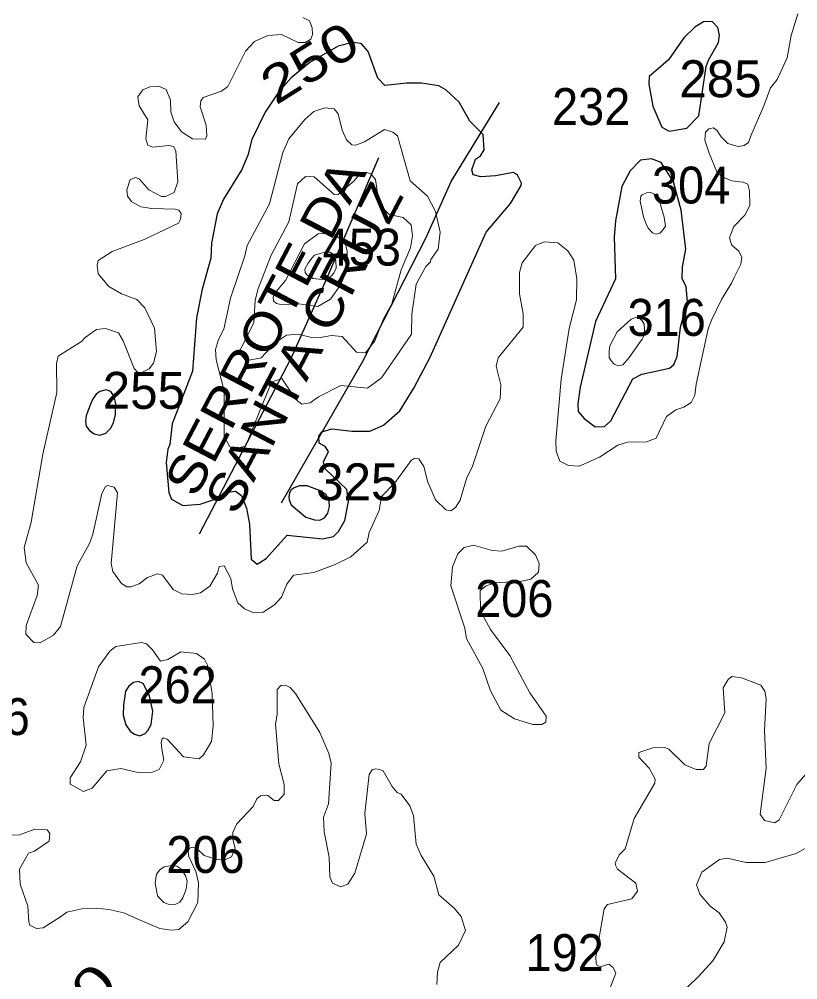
# Model space of a CAD drawing. Extents: x 499.9 to 555.3, y 9281.5 to 9336.8.
# Drawn here: x 532.96 to 536.335, y 9313.886 to 9318.048 of the extents above; entities that cross this region are included whole.
import ezdxf
from ezdxf.enums import TextEntityAlignment as Align

# ---------------------------------------------------------------- set-up
doc = ezdxf.new("R2010")
doc.units = 0
doc.header["$LTSCALE"] = 0.064
for name, color, linetype, lineweight in [('1', 7, 'Continuous', 25), ('2', 7, 'Continuous', 13), ('26', 7, 'Continuous', 25)]:
    doc.layers.add(name, color=color, linetype=linetype, lineweight=lineweight)
doc.layers.add('21', color=7, linetype='Continuous')
doc.layers.add('61', color=7, linetype='Continuous')

msp = doc.modelspace()

# ---------------------------------------------------------------- linework, layer by layer
at = {"layer": '1'}
for points in [[(535.8544, 9317.5765), (535.9065, 9317.6293), (535.9382, 9317.8433), (535.9476, 9317.8711), (535.9909, 9317.9476), (535.9952, 9317.9793), (535.9889, 9318.0125), (535.9645, 9318.0388), (535.9266, 9318.037), (535.889, 9318.0138), (535.8404, 9317.9681), (535.7749, 9317.872), (535.7521, 9317.8519), (535.6906, 9317.8007), (535.6888, 9317.7675), (535.706, 9317.6708), (535.7456, 9317.58), (535.7777, 9317.5636)], [(534.4723, 9317.9086), (534.4426, 9317.9428), (534.4053, 9317.9469), (534.3422, 9317.9319), (534.2194, 9317.8603), (534.1392, 9317.7937), (534.0832, 9317.7318), (534.0264, 9317.6453), (533.9684, 9317.5274), (533.9505, 9317.4598), (533.9253, 9317.3969), (533.8455, 9317.2688), (533.8185, 9317.2051), (533.793, 9317.0778), (533.7911, 9317.0134), (533.7527, 9316.8785), (533.7279, 9316.7539), (533.7117, 9316.5231), (533.6235, 9316.2949), (533.6123, 9316.2054), (533.6035, 9316.1857), (533.5972, 9316.1271), (533.6078, 9315.9968), (533.6198, 9315.9688), (533.6684, 9315.9416), (533.7444, 9315.9466), (533.8136, 9315.9702), (533.8741, 9316.0005), (533.897, 9316.0029), (533.9236, 9315.9838), (533.9454, 9315.9295), (533.9583, 9315.8596), (533.9658, 9315.7079), (533.9913, 9315.6875), (534.03, 9315.7108), (534.122, 9315.8118), (534.2743, 9315.7962), (534.3222, 9315.8068), (534.3435, 9315.8277), (534.371, 9315.8766), (534.3868, 9315.9584), (534.3795, 9316.0102), (534.2863, 9316.1005), (534.2793, 9316.1304), (534.3008, 9316.1748), (534.2861, 9316.1972), (534.2597, 9316.2113), (534.2586, 9316.2408), (534.2721, 9316.2606), (534.3149, 9316.2738), (534.4022, 9316.2636), (534.4797, 9316.2634), (534.5392, 9316.2886), (534.6098, 9316.3511), (534.671, 9316.45), (534.7412, 9316.5837), (534.9847, 9317.1249), (535.0901, 9317.2498), (535.1364, 9317.3273), (535.1373, 9317.3379), (535.1195, 9317.3722), (535.1026, 9317.3845), (535.0241, 9317.3692), (534.9607, 9317.3646), (534.9281, 9317.3742), (534.9216, 9317.3952), (534.9379, 9317.4411), (534.9594, 9317.4568), (534.9751, 9317.4823), (534.9706, 9317.548), (534.9136, 9317.6063), (534.8671, 9317.6889), (534.8093, 9317.7419), (534.7791, 9317.7594), (534.7041, 9317.7717), (534.639, 9317.7717), (534.5452, 9317.7614), (534.514, 9317.7925)], [(535.6206, 9316.4906), (535.659, 9316.5098), (535.7787, 9316.5366), (535.7971, 9316.5522), (535.8124, 9316.586), (535.8261, 9316.7136), (535.8572, 9316.8242), (535.8514, 9316.8879), (535.8335, 9316.9242), (535.835, 9316.9753), (535.8497, 9317.0521), (535.8302, 9317.2209), (535.7969, 9317.344), (535.7428, 9317.4279), (535.701, 9317.4431), (535.6529, 9317.4372), (535.6089, 9317.3914), (535.5718, 9317.3231), (535.5454, 9317.1743), (535.539, 9317.1042), (535.5452, 9316.9226), (535.4587, 9316.7383), (535.3923, 9316.4531), (535.3815, 9316.3816), (535.3833, 9316.349), (535.4085, 9316.3174), (535.4562, 9316.2824), (535.4974, 9316.284), (535.5241, 9316.3079)], [(533.2701, 9316.3833), (533.2569, 9316.3505), (533.2506, 9316.3302), (533.2475, 9316.3068), (533.2506, 9316.2842), (533.2647, 9316.2655), (533.2849, 9316.2515), (533.3091, 9316.246), (533.3348, 9316.2546), (533.3551, 9316.2741), (533.3691, 9316.299), (533.3769, 9316.3357), (533.3785, 9316.3817), (533.3715, 9316.4129), (533.3567, 9316.4347), (533.3372, 9316.4417), (533.3091, 9316.4355), (533.2927, 9316.4238), (533.2771, 9316.4004)], [(534.1381, 9315.9435), (534.2022, 9315.8912), (534.2406, 9315.8784), (534.263, 9315.8773), (534.2833, 9315.888), (534.2983, 9315.9083), (534.3047, 9315.936), (534.3036, 9315.9617), (534.2887, 9315.9884), (534.2609, 9316.0065), (534.2075, 9316.0257), (534.1744, 9316.0257), (534.152, 9316.0182), (534.1381, 9316.0086), (534.1317, 9315.9958), (534.1285, 9315.9798), (534.1307, 9315.9649)], [(533.4178, 9315.1168), (533.4114, 9315.0774), (533.4101, 9315.0329), (533.4216, 9314.9909), (533.4407, 9314.9629), (533.4597, 9314.9502), (533.4826, 9314.9426), (533.5055, 9314.9527), (533.517, 9314.9655), (533.5322, 9314.9922), (533.5386, 9315.0494), (533.5246, 9315.1155), (533.4992, 9315.1677), (533.4775, 9315.1779), (533.4559, 9315.174), (533.4343, 9315.1575), (533.4203, 9315.1372)]]:
    msp.add_lwpolyline(points, close=True, dxfattribs=at)
at = {"layer": '2'}
for points in [[(536.3346, 9318.0718), (536.3065, 9317.9773), (536.2887, 9317.8808), (536.245, 9317.7871), (536.2174, 9317.7502), (536.188, 9317.6723), (536.1319, 9317.5431), (536.1209, 9317.5135), (536.103, 9317.5013), (536.0762, 9317.4967), (536.0319, 9317.5104), (536.0023, 9317.5386), (535.9845, 9317.5677), (535.9677, 9317.5769), (535.9491, 9317.5739), (535.9357, 9317.5588), (535.9317, 9317.5242), (535.9512, 9317.4673), (535.9838, 9317.3864), (536.006, 9317.3672), (536.0481, 9317.3483), (536.099, 9317.3419), (536.1179, 9317.3337), (536.126, 9317.3048), (536.1274, 9317.2403), (536.1053, 9317.1989), (536.0584, 9317.15), (536.0386, 9317.102), (536.0476, 9317.0707), (536.0792, 9317.0437), (536.0927, 9317.0151), (536.0882, 9316.9866), (536.0597, 9316.9295), (536.0477, 9316.9038), (536.004, 9316.8334), (535.961, 9316.7443), (535.9469, 9316.707), (535.8945, 9316.4673), (535.8888, 9316.419)], [(533.2303, 9316.651), (533.2451, 9316.6696), (533.2942, 9316.7033), (533.3344, 9316.7084), (533.3906, 9316.6886), (533.4105, 9316.6551), (533.4582, 9316.5351), (533.4738, 9316.5167), (533.4908, 9316.5167), (533.5236, 9316.5334), (533.5414, 9316.5577), (533.5543, 9316.609), (533.5459, 9316.7094), (533.5047, 9316.7976), (533.4697, 9316.8341), (533.4031, 9316.8583), (533.3476, 9316.8898), (533.3025, 9316.945), (533.2981, 9316.9806), (533.3024, 9317.0023), (533.3632, 9317.0419), (533.5016, 9317.093), (533.6498, 9317.1646), (533.6584, 9317.1813), (533.6615, 9317.2061), (533.6516, 9317.2212), (533.6352, 9317.2257), (533.5343, 9317.2275), (533.4877, 9317.2351), (533.4477, 9317.2562), (533.4287, 9317.2816), (533.4259, 9317.3087), (533.4404, 9317.354), (533.465, 9317.3624), (533.4812, 9317.3553), (533.5215, 9317.3083), (533.5764, 9317.28), (533.594, 9317.2802), (533.6314, 9317.2975), (533.6467, 9317.3442), (533.6385, 9317.4781), (533.6292, 9317.4971), (533.609, 9317.5013), (533.5386, 9317.4933), (533.5171, 9317.5027), (533.5084, 9317.5306), (533.5174, 9317.6124), (533.48, 9317.6725), (533.4742, 9317.7114), (533.4956, 9317.7421), (533.5262, 9317.7555), (533.5653, 9317.7587), (533.5966, 9317.7433), (533.6156, 9317.6978), (533.6164, 9317.6476), (533.6311, 9317.6033), (533.6633, 9317.5599), (533.7112, 9317.5302), (533.7671, 9317.5287), (533.7736, 9317.5426), (533.7706, 9317.5895), (533.7442, 9317.6683), (533.747, 9317.6945), (533.7579, 9317.7089), (533.8368, 9317.7364), (533.8649, 9317.7565), (533.9401, 9317.9101), (533.9802, 9317.951), (534.0372, 9317.977), (534.0965, 9317.9816), (534.1696, 9317.9467), (534.1994, 9317.9467), (534.2233, 9317.9616), (534.231, 9317.9818), (534.2297, 9318.0109), (534.2188, 9318.0409), (534.1897, 9318.0562)], [(535.721, 9316.2323), (535.6789, 9316.217), (535.597, 9316.2151), (535.5556, 9316.2027), (535.4759, 9316.1503), (535.3869, 9316.1121), (535.3416, 9316.1151), (535.3032, 9316.1333), (535.2876, 9316.1771), (535.2859, 9316.2209), (535.3097, 9316.4882), (535.3437, 9316.7087), (535.3763, 9316.832), (535.3765, 9316.9226), (535.3638, 9317.0045), (535.3378, 9317.0447), (535.2951, 9317.0792), (535.2349, 9317.0841), (535.1979, 9317.0677), (535.1405, 9316.9933), (535.1285, 9316.9513), (535.1287, 9316.858), (535.1441, 9316.7722), (535.1444, 9316.7131), (535.0361, 9316.5811), (535.0268, 9316.5455), (535.0484, 9316.4643), (535.0455, 9316.4037), (534.9832, 9316.2845), (534.9232, 9316.1078), (534.9004, 9316.0617), (534.8716, 9315.9648), (534.8512, 9315.9321), (534.8306, 9315.918), (534.8094, 9315.9229), (534.7641, 9315.9651), (534.7308, 9316.0426), (534.7146, 9316.1094), (534.6921, 9316.143), (534.6717, 9316.1449), (534.6584, 9316.1355), (534.5882, 9316.0394), (534.5307, 9315.9805), (534.5207, 9315.9192), (534.4774, 9315.8238), (534.4676, 9315.7825), (534.3978, 9315.7184), (534.3296, 9315.6847), (534.237, 9315.6503), (534.1482, 9315.6386), (534.1194, 9315.6008), (534.0967, 9315.5436), (534.0666, 9315.5102), (534.0173, 9315.4786), (533.9768, 9315.4753), (533.9363, 9315.4928), (533.9073, 9315.5187), (533.8842, 9315.5799), (533.8775, 9315.6244), (533.8479, 9315.6802), (533.8267, 9315.6768), (533.8195, 9315.648), (533.7859, 9315.591), (533.7452, 9315.5629), (533.7103, 9315.5551), (533.6648, 9315.558), (533.6266, 9315.5768), (533.5814, 9315.6398), (533.5589, 9315.6451), (533.5153, 9315.6297), (533.4794, 9315.6009), (533.4445, 9315.5883), (533.4263, 9315.5887), (533.4037, 9315.6037), (533.3656, 9315.6555), (533.3585, 9315.69), (533.3852, 9315.9962), (533.3715, 9316.0206), (533.3425, 9316.0281), (533.3338, 9316.0227), (533.3185, 9315.9931), (533.2788, 9315.8173), (533.2641, 9315.776), (533.2109, 9315.6803), (533.139, 9315.417), (533.1079, 9315.3793), (533.0512, 9315.3465), (533.0234, 9315.3469), (532.9878, 9315.3838), (532.9894, 9315.4209), (533.0375, 9315.5508), (533.0431, 9315.5952), (532.9896, 9315.6925), (532.9814, 9315.7584), (533.0114, 9315.8682)], [(533.0114, 9315.8682), (533.0623, 9316.1636), (533.1227, 9316.4309), (533.1211, 9316.5566), (533.1292, 9316.5884), (533.2303, 9316.651)], [(535.8888, 9316.419), (535.8733, 9316.3877), (535.8412, 9316.3665), (535.8064, 9316.3551), (535.7657, 9316.327), (535.721, 9316.2323)], [(535.5179, 9313.8389), (535.547, 9313.9139), (535.5347, 9313.9396), (535.5156, 9313.9542), (535.4821, 9313.943), (535.4675, 9313.9463), (535.4608, 9313.9564), (535.4597, 9313.9853), (535.4961, 9314.1935), (535.5099, 9314.2123), (535.6159, 9314.2368), (535.6403, 9314.2704), (535.6337, 9314.3041), (535.554, 9314.3657), (535.5459, 9314.3796), (535.5438, 9314.3907), (535.5604, 9314.4266), (535.5871, 9314.4535), (535.6262, 9314.5847), (535.7154, 9314.7382), (535.7166, 9314.7548), (535.6903, 9314.8027), (535.6461, 9314.8508), (535.6464, 9314.8705), (535.7069, 9314.8908), (535.7591, 9314.8923), (535.7765, 9314.8855), (535.8453, 9314.8176), (535.895, 9314.7975), (535.9269, 9314.7977), (535.9373, 9314.8133), (535.9512, 9314.9092), (536.0195, 9315.043), (536.012, 9315.1512), (536.0336, 9315.1873), (536.0491, 9315.1995), (536.0911, 9315.1949), (536.1747, 9315.1632), (536.1916, 9315.1368), (536.1978, 9315.1036), (536.1914, 9314.9662), (536.1977, 9314.8019), (536.1724, 9314.603), (536.1901, 9314.5762), (536.236, 9314.5667), (536.2544, 9314.5787), (536.3316, 9314.7318), (536.3805, 9314.7891)], [(532.9161, 9314.5124), (532.9606, 9314.514), (533.0268, 9314.5389), (533.0806, 9314.536), (533.0924, 9314.5193), (533.0903, 9314.4865), (533.0255, 9314.4431), (532.9993, 9314.434), (532.9607, 9314.3651), (532.9637, 9314.2997), (532.9978, 9314.2055), (533.0014, 9314.1372), (533.0062, 9314.1222), (533.0354, 9314.108), (533.064, 9314.1111), (533.1393, 9314.159), (533.166, 9314.1782), (533.231, 9314.1931), (533.2928, 9314.1961), (533.3479, 9314.1908), (533.4127, 9314.1759), (533.4739, 9314.148), (533.5693, 9314.1078), (533.618, 9314.1002), (533.6519, 9314.1038), (533.691, 9314.1368), (533.7335, 9314.2208), (533.7373, 9314.3063), (533.7249, 9314.3558), (533.6944, 9314.4207), (533.692, 9314.4421), (533.6986, 9314.4569), (533.7114, 9314.4604), (533.7316, 9314.4533), (533.7618, 9314.4245), (533.8161, 9314.4075), (533.8486, 9314.4043), (533.8796, 9314.4181), (533.8962, 9314.4565), (533.8838, 9314.5011), (533.886, 9314.5241), (533.9029, 9314.5614), (533.9743, 9314.6365), (533.9894, 9314.6702), (534.0057, 9314.6836), (534.038, 9314.6839), (534.0646, 9314.6625), (534.0842, 9314.6634), (534.1077, 9314.6907), (534.1079, 9314.7319), (534.0858, 9314.8218), (534.0715, 9314.9929), (534.0778, 9315.035), (534.078, 9315.1234), (534.0786, 9315.1439), (534.0936, 9315.1608), (534.1137, 9315.163), (534.1348, 9315.1524), (534.1578, 9315.1259), (534.2627, 9314.9572), (534.3026, 9314.8669), (534.3117, 9314.8242), (534.301, 9314.6485), (534.2787, 9314.5901), (534.2818, 9314.5274), (534.2832, 9314.5196), (534.3038, 9314.4167), (534.307, 9314.3317), (534.3177, 9314.3049), (534.3535, 9314.288), (534.3851, 9314.3009)], [(534.3851, 9314.3009), (534.4141, 9314.3485), (534.466, 9314.5179), (534.4584, 9314.6063), (534.4774, 9314.7755), (534.49, 9314.7961)], [(534.49, 9314.7961), (534.5063, 9314.8003), (534.5222, 9314.7971), (534.5378, 9314.7915), (534.5763, 9314.723), (534.5979, 9314.6975), (534.6161, 9314.6899), (534.6538, 9314.6395), (534.6684, 9314.5974), (534.6812, 9314.4741), (534.7021, 9314.4249), (534.757, 9314.3347), (534.7786, 9314.254), (534.8448, 9314.1955), (534.8762, 9314.1595), (534.894, 9314.1), (534.8643, 9314.0355), (534.7847, 9313.9614), (534.7733, 9313.9194), (534.7701, 9313.8653)], [(536.3665, 9314.455), (536.3275, 9314.4325), (536.1939, 9314.3945), (536.1118, 9314.3945), (536.0291, 9314.4133), (535.9964, 9314.4073), (535.9184, 9314.3519), (535.8955, 9314.298), (535.91, 9314.2575), (535.9559, 9314.2051), (535.9936, 9314.1764), (536.0216, 9314.1352), (536.029, 9314.1137), (536.0164, 9314.0507), (535.9666, 9313.9679), (535.9049, 9313.8995), (535.8177, 9313.8166)]]:
    msp.add_lwpolyline(points, dxfattribs=at)
for points in [[(534.6624, 9316.7701), (534.6809, 9316.9008), (534.7221, 9316.9772), (534.7425, 9316.9962), (534.7438, 9317.0067), (534.7759, 9317.052), (534.7843, 9317.1256), (534.7649, 9317.2154), (534.7296, 9317.2819), (534.6541, 9317.3486), (534.5995, 9317.5422), (534.579, 9317.5584), (534.5427, 9317.5708), (534.4565, 9317.5165), (534.4192, 9317.5031), (534.4016, 9317.5045), (534.3787, 9317.5251), (534.3599, 9317.5673), (534.3425, 9317.6381), (534.325, 9317.6603), (534.2848, 9317.6649), (534.2365, 9317.6486), (534.1973, 9317.6141), (534.1285, 9317.5298), (534.1021, 9317.4701), (534.045, 9317.2483), (533.9473, 9317.0675), (533.9376, 9317.023), (533.876, 9316.8399), (533.8469, 9316.7055), (533.8231, 9316.6601), (533.8107, 9316.6171), (533.8135, 9316.5724), (533.8487, 9316.4373), (533.8487, 9316.2398), (533.8724, 9316.1954), (533.8996, 9316.1884), (533.9412, 9316.1986), (534.0542, 9316.476), (534.0987, 9316.4914), (534.1586, 9316.4006), (534.1852, 9316.3795), (534.2217, 9316.386), (534.2573, 9316.4125), (534.3541, 9316.4615), (534.4693, 9316.4494), (534.5303, 9316.4944), (534.6602, 9316.6841)], [(534.5753, 9316.8153), (534.6158, 9316.9616), (534.6564, 9317.0571), (534.665, 9317.1096), (534.6596, 9317.1578), (534.6236, 9317.189), (534.5643, 9317.2027), (534.5203, 9317.2474), (534.5047, 9317.3532), (534.4841, 9317.3785), (534.4629, 9317.3853), (534.4403, 9317.3827), (534.4121, 9317.3485), (534.3414, 9317.2866), (534.3245, 9317.2894), (534.2391, 9317.3652), (534.2015, 9317.367), (534.1669, 9317.3349), (534.1289, 9317.1709), (534.052, 9317.0262), (533.9936, 9316.8773), (533.9823, 9316.8288), (533.9771, 9316.7334), (533.9128, 9316.6052), (533.9428, 9316.5675), (534.0081, 9316.5809), (534.071, 9316.6474), (534.119, 9316.6793), (534.1701, 9316.683), (534.2214, 9316.6703), (534.2649, 9316.6689), (534.3134, 9316.6782), (534.3603, 9316.6734), (534.4224, 9316.6062), (534.4612, 9316.6024), (534.5015, 9316.6553), (534.5392, 9316.7493)], [(535.6522, 9317.26), (535.6659, 9317.1926), (535.6762, 9317.1641), (535.6865, 9317.1435), (535.7059, 9317.1229), (535.7207, 9317.1161), (535.7367, 9317.1218), (535.7481, 9317.1332), (535.7618, 9317.1515), (535.7561, 9317.1903), (535.7356, 9317.2588), (535.7264, 9317.2782), (535.7127, 9317.2908), (535.6956, 9317.2988), (535.6796, 9317.2965), (535.6602, 9317.2874), (535.6545, 9317.2811)], [(534.3093, 9316.8346), (534.3535, 9316.8993), (534.375, 9316.9481), (534.3825, 9316.9954), (534.3809, 9317.045), (534.3718, 9317.083), (534.3158, 9317.1207), (534.2552, 9317.1176), (534.1964, 9317.0752), (534.1148, 9316.9163), (534.0658, 9316.8601), (534.061, 9316.8433), (534.0623, 9316.8273), (534.0753, 9316.8167), (534.0945, 9316.8123), (534.1715, 9316.8153), (534.2543, 9316.8027)], [(534.293, 9316.9241), (534.3122, 9316.935), (534.3239, 9316.9475), (534.3339, 9316.9701), (534.3323, 9317.0018), (534.3247, 9317.0277), (534.308, 9317.0386), (534.2846, 9317.0386), (534.2638, 9317.0336), (534.2395, 9317.0261), (534.2287, 9317.0127), (534.2128, 9316.9918), (534.1978, 9316.9651), (534.1994, 9316.95), (534.2061, 9316.94), (534.2337, 9316.9241), (534.2729, 9316.9208)], [(535.5393, 9316.5541), (535.5496, 9316.5489), (535.563, 9316.5479), (535.5764, 9316.551), (535.6042, 9316.5829), (535.6486, 9316.6458), (535.6599, 9316.6623), (535.6692, 9316.6798), (535.6712, 9316.7045), (535.6692, 9316.7261), (535.6609, 9316.7406), (535.6506, 9316.7519), (535.6321, 9316.755), (535.6125, 9316.7488), (535.5517, 9316.6942), (535.5198, 9316.6334), (535.5167, 9316.6107), (535.5167, 9316.5819), (535.5259, 9316.5675)], [(534.8995, 9315.3646), (534.891, 9315.4099), (534.8312, 9315.5926), (534.8386, 9315.6749), (534.8611, 9315.7313), (534.8881, 9315.7597), (534.9292, 9315.7691), (535.0105, 9315.7458), (535.0524, 9315.7425), (535.1251, 9315.7647), (535.1588, 9315.7644), (535.1985, 9315.7275), (535.2142, 9315.6892), (535.2116, 9315.6528), (535.1774, 9315.6224), (535.1371, 9315.6137), (535.024, 9315.6057), (534.9845, 9315.5924), (534.9581, 9315.5726), (534.9595, 9315.4837), (535.0031, 9315.4033), (535.0865, 9315.2912), (535.1733, 9315.1291), (535.2438, 9315.0286), (535.2432, 9315.0021), (535.2258, 9314.9925), (535.1864, 9314.992), (535.1068, 9315.0165), (535.0483, 9315.054), (535.0035, 9315.1376), (534.9691, 9315.2348)], [(533.8007, 9314.9846), (533.7961, 9315.1244), (533.7767, 9315.2486), (533.7625, 9315.2759), (533.7283, 9315.2996), (533.6608, 9315.3064), (533.6035, 9315.2733), (533.5726, 9315.2671), (533.5383, 9315.3159), (533.5119, 9315.3421), (533.4899, 9315.3477), (533.3788, 9315.3307), (533.3526, 9315.3098), (533.304, 9315.242), (533.2406, 9315.0653), (533.2375, 9315.0223), (533.2501, 9314.9023), (533.2249, 9314.8296), (533.1811, 9314.7604), (533.1806, 9314.7337), (533.2383, 9314.7017), (533.2756, 9314.7162), (533.3396, 9314.7912), (533.3998, 9314.8019), (533.4675, 9314.786), (533.5305, 9314.7829), (533.5659, 9314.7977), (533.5873, 9314.8372), (533.5786, 9314.8873), (533.5755, 9314.9139), (533.5792, 9314.9302), (533.5848, 9314.9337), (533.6008, 9314.9282), (533.6716, 9314.8517), (533.7403, 9314.8436), (533.759, 9314.8609), (533.7936, 9314.9191)], [(533.5494, 9314.3041), (533.5595, 9314.2498), (533.5703, 9314.2365), (533.587, 9314.2206), (533.6062, 9314.2131), (533.6288, 9314.2106), (533.6388, 9314.2139), (533.6555, 9314.2222), (533.6689, 9314.2415), (533.6839, 9314.2782), (533.6881, 9314.3133), (533.6806, 9314.3384), (533.6597, 9314.3668), (533.643, 9314.3776), (533.6204, 9314.3818), (533.5887, 9314.3751), (533.5695, 9314.3626), (533.5549, 9314.3439)]]:
    msp.add_lwpolyline(points, close=True, dxfattribs=at)
at = {"layer": '26'}
for points in [[(534.0969, 9315.9524), (534.4482, 9316.5629), (534.7241, 9317.1023), (534.8329, 9317.3449), (535.0419, 9317.6878)], [(533.7415, 9315.8186), (534.1387, 9316.5796), (534.293, 9316.9241), (534.5192, 9317.4494)]]:
    msp.add_lwpolyline(points, dxfattribs=at)

# ---------------------------------------------------------------- texts
at = {"layer": '21'}
for s, p in [('285', (535.8214, 9317.7104)), ('255', (533.3218, 9316.36)), ('325', (534.2469, 9315.9635))]:
    msp.add_text(s, height=0.16, dxfattribs=at).set_placement(p)
at = {"layer": '21', "width": 0.95}
for s, p in [('232', (535.2698, 9317.5897)), ('304', (535.7031, 9317.2495)), ('453', (534.2756, 9316.9806)), ('316', (535.5973, 9316.6761)), ('206', (534.9365, 9315.4579)), ('262', (533.4769, 9315.0844)), ('186', (532.6667, 9314.9464)), ('206', (533.5976, 9314.3488)), ('192', (535.1548, 9313.9236))]:
    msp.add_text(s, height=0.16, dxfattribs=at).set_placement(p)
at = {"layer": '26', "width": 1.15}
for s, p in [('SERROTE DA', (534.0965, 9316.6765)), ('SANTA CRUZ', (534.2647, 9316.5882))]:
    msp.add_text(s, height=0.16, rotation=62.301, dxfattribs=at).set_placement(p, align=Align.CENTER)
at = {"layer": '61'}
for s, rotation, width, p in [('250', 32.196, 1.25, (534.2613, 9317.7922)), ('150', 47.291, 1.35, (533.2314, 9313.6874))]:
    msp.add_text(s, height=0.16, rotation=rotation, dxfattribs=dict(at, width=width)).set_placement(p, align=Align.CENTER)

doc.saveas('drawing.dxf')
